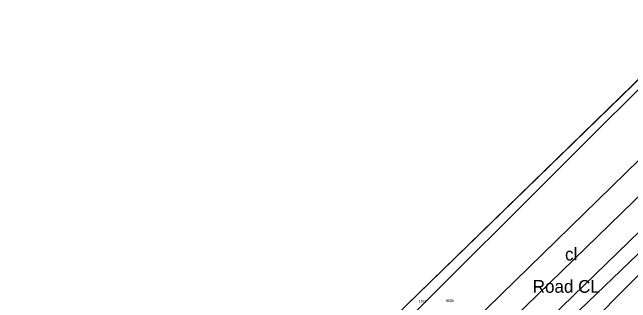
# Model space of a CAD drawing. Extents: x 2500794 to 2511032, y 910653 to 917533.
# Drawn here: x 2504774.7 to 2505017.8, y 912673.7 to 912787.9 of the extents above; entities that cross this region are included whole.
import ezdxf

# ---------------------------------------------------------------- set-up
doc = ezdxf.new("R2010")
doc.units = 0
for name, color, linetype in [('Default', 7, 'Continuous'), ('RD_EX_DV_Prop', 7, 'Continuous'), ('RD_EX_H2O_txCode', 7, 'Continuous'), ('RD_EX_Road', 7, 'Continuous'), ('RD_EX_RW', 7, 'Continuous'), ('RD_EX_VEG', 7, 'Continuous'), ('RD_EX_VEG_txCode', 7, 'Continuous'), ('RD_HC_Cl', 7, 'Continuous')]:
    doc.layers.add(name, color=color, linetype=linetype)

# ---------------------------------------------------------------- blocks, each defined once
blk = doc.blocks.new('POINT_DISPLAY')
at = {"layer": 'Default'}
blk.add_line((0, 0), (0, 0), dxfattribs=at)

msp = doc.modelspace()

# ---------------------------------------------------------------- linework, layer by layer
at = {"layer": 'RD_EX_DV_Prop'}
msp.add_line((2503534.53, 911315.65), (2505206.65, 912942.11), dxfattribs=at)
at = {"layer": 'RD_EX_H2O_txCode'}
msp.add_line((2505041.64, 912712.98), (2504976.13, 912650.13), dxfattribs=at)
msp.add_lwpolyline([(2505042.85, 912708.63), (2505038.44, 912702.17), (2504980.48, 912643.76), (2504977.77, 912645.86), (2504976.13, 912650.13)], dxfattribs=at)
at = {"layer": 'RD_EX_Road'}
for points in [[(2505356.25, 913055.37), (2505297.36, 912998.59), (2505254.44, 912956.44), (2505177.06, 912881.21), (2505102.21, 912808.73), (2505026.72, 912735.2), (2504956.07, 912666.21), (2504882.83, 912595.14), (2504825.46, 912547.52), (2504807.83, 912522.24), (2504732.55, 912448.69), (2504654.06, 912372.59), (2504585.1, 912305.45), (2504533.51, 912254.98)], [(2505370.6, 913041.78), (2505311.87, 912984.11), (2505268.01, 912941.43), (2505190.92, 912867.21), (2505116.28, 912794.43), (2505039.14, 912719.03), (2504973.12, 912654.77), (2504957.32, 912639.49), (2504897.44, 912581.22), (2504858.98, 912543.75), (2504838.29, 912523.7), (2504810.7, 912496.65), (2504795.8, 912482.32), (2504747.07, 912434.9), (2504696.6, 912386.17), (2504686.81, 912376.67), (2504668.39, 912358.37), (2504598.36, 912290.29), (2504547.08, 912240.34)]]:
    msp.add_lwpolyline(points, dxfattribs=at)
at = {"layer": 'RD_EX_RW'}
msp.add_line((2504517.34, 912271.63), (2505206.66, 912942.12), dxfattribs=at)
at = {"layer": 'RD_EX_VEG'}
msp.add_lwpolyline([(2505339.13, 913074.53), (2505242.44, 912974.3), (2505088.02, 912824.67), (2504935.82, 912672.7), (2504815.59, 912550.95), (2504817.4, 912591.81)], dxfattribs=at)
at = {"layer": 'RD_HC_Cl'}
msp.add_line((2504540.35, 912247.97), (2505598.79, 913277.5), dxfattribs=at)

# ---------------------------------------------------------------- block references
at = {"layer": 'Default', "xscale": 3.937007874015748, "yscale": 3.937007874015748}
for p in [(2504992.03, 912690.25), (2504992.03, 912690.25), (2504979.33, 912677.54), (2504979.33, 912677.54)]:
    msp.add_blockref('POINT_DISPLAY', p, dxfattribs=at)

# ---------------------------------------------------------------- texts
at = {"layer": 'Default'}
for s, p in [('cl', (2504992.03, 912690.25)), ('cl', (2504992.03, 912690.25)), ('Road CL', (2504979.33, 912677.54)), ('Road CL', (2504979.33, 912677.54))]:
    msp.add_text(s, height=5, dxfattribs=at).set_placement(p)
at = {"layer": 'RD_EX_H2O_txCode'}
for s, p in [('1570', (2504944.95, 912673.86)), ('1571', (2504945.28, 912673.86))]:
    msp.add_text(s, height=1, dxfattribs=at).set_placement(p)
at = {"layer": 'RD_EX_VEG_txCode'}
msp.add_text('1574', height=1, dxfattribs=at).set_placement((2504934.47, 912673.7))

doc.saveas('drawing.dxf')
